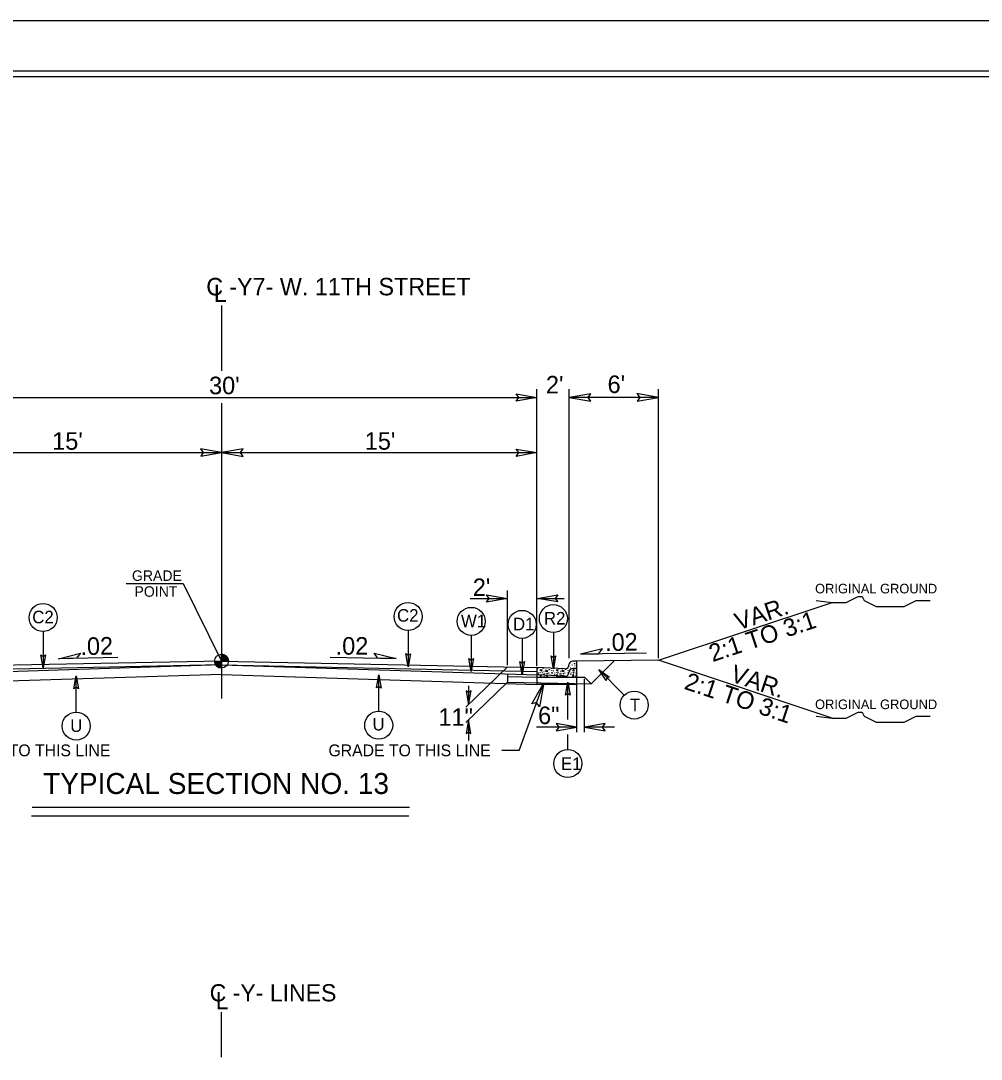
# Model space of a CAD drawing. Extents: x 957297 to 961629, y 830661 to 840840.
# Drawn here: x 959348.5 to 959775.5, y 833917.1 to 834378.9 of the extents above; entities that cross this region are included whole.
import ezdxf

# ---------------------------------------------------------------- set-up
doc = ezdxf.new("R2010")
doc.units = 0
for name, color, linetype in [('Default', 7, 'Continuous'), ('Old_Level_1', 7, 'Continuous'), ('Old_Level_11', 7, 'Continuous'), ('Old_Level_21', 7, 'Continuous'), ('Old_Level_3', 7, 'Continuous'), ('Prop Dimension Text', 7, 'Continuous'), ('Sheet Plot Border Inside CELL', 7, 'Continuous'), ('Sheet Plot Border Outside CELL', 7, 'Continuous'), ('Sheet Typical CELL', 7, 'Continuous'), ('Typical ID Circle CELL', 7, 'Continuous'), ('Typical Terminator CELL', 7, 'Continuous'), ('Typical Text Grade Point CELL', 7, 'Continuous'), ('Typical Text ID Circle CELL', 7, 'Continuous')]:
    doc.layers.add(name, color=color, linetype=linetype)

msp = doc.modelspace()

# ---------------------------------------------------------------- linework, layer by layer
at = {"layer": 'Default'}
for p, q in [((959437.72, 834252.24), (959437.72, 834223.26)), ((959437.72, 834208.87), (959437.72, 834077.5)), ((959437.72, 833918.09), (959437.72, 833938.07))]:
    msp.add_line(p, q, dxfattribs=at)
at = {"layer": 'Old_Level_1'}
for p, q in [((959577.94, 834092.06), (959577.94, 834215.05)), ((959592.24, 834095.46), (959592.24, 834215.05)), ((959632.06, 834095.46), (959632.06, 834215.05)), ((959297.55, 834211.42), (959577.94, 834211.42)), ((959632.06, 834211.42), (959592.24, 834211.42)), ((959297.5, 834186.86), (959437.72, 834186.86)), ((959437.72, 834186.86), (959577.94, 834186.86)), ((959564.8, 834092.3), (959564.8, 834125.5)), ((959548.26, 834122.04), (959564.8, 834122.04)), ((959578, 834122.04), (959590.11, 834122.04)), ((959632.06, 834094.54), (959709.25, 834120.27)), ((959437.72, 834094.16), (959437.72, 834097.22)), ((959626.59, 834097.76), (959597.37, 834097.18)), ((959437.72, 834094.17), (959297.55, 834091.33)), ((959437.72, 834092.44), (959297.55, 834089.61)), ((959437.72, 834092.44), (959297.55, 834088.05)), ((959391.59, 834095.77), (959365.21, 834095.24)), ((959434.66, 834094.16), (959437.72, 834094.16)), ((959437.72, 834094.17), (959577.94, 834091.33)), ((959440.78, 834094.16), (959437.72, 834094.16)), ((959437.72, 834091.11), (959437.72, 834094.16)), ((959437.72, 834094.16), (959437.72, 834091.11)), ((959437.72, 834092.44), (959577.94, 834089.61)), ((959437.72, 834092.44), (959577.94, 834088.05)), ((959486.07, 834095.86), (959515.29, 834095.28)), ((959632.06, 834094.54), (959595.74, 834094.18)), ((959602.01, 834084.02), (959612.34, 834094.35)), ((959709.25, 834068.81), (959632.06, 834094.54)), ((959437.72, 834088.17), (959297.55, 834083.77)), ((959437.72, 834088.17), (959577.88, 834083.77)), ((959564.82, 834091.6), (959546.35, 834073.67)), ((959564.8, 834088.46), (959564.8, 834084.77)), ((959590.33, 834087.43), (959577.94, 834088.05)), ((959577.94, 834088.05), (959577.94, 834083.94)), ((959595.43, 834090.89), (959593.96, 834090.89)), ((959595.74, 834087.33), (959595.74, 834090.59)), ((959564.8, 834084.77), (959546.32, 834066.84)), ((959547.56, 834083.21), (959547.56, 834074.84)), ((959564.8, 834087.32), (959577.94, 834087.06)), ((959564.8, 834084.77), (959602.01, 834084.02)), ((959569.99, 834054.41), (959580.97, 834084.44)), ((959577.94, 834087.06), (959577.94, 834084.51)), ((959577.94, 834083.94), (959595.74, 834083.94)), ((959595.74, 834083.94), (959595.74, 834087.33)), ((959595.74, 834087.06), (959599.04, 834086.99)), ((959595.74, 834062.5), (959595.74, 834086.26)), ((959599.04, 834086.99), (959602.01, 834084.02)), ((959599.04, 834062.5), (959599.04, 834086.26)), ((959547.5, 834068.02), (959547.49, 834058.8)), ((959595.74, 834064.79), (959577.72, 834064.79)), ((959612.38, 834064.79), (959599.04, 834064.79)), ((959569.99, 834054.41), (959562.27, 834054.41)), ((959521.22, 834029.03), (959353.52, 834029.03)), ((959520.94, 834025.23), (959353.24, 834025.23))]:
    msp.add_line(p, q, dxfattribs=at)
for points in [[(959437.76, 834097.22), (959437.76, 834097.22), (959437.76, 834094.16)], [(959437.81, 834097.22), (959437.81, 834094.16)], [(959437.87, 834097.22), (959437.87, 834094.16)], [(959437.94, 834097.21), (959437.94, 834094.16)], [(959438, 834097.21), (959438, 834094.16)], [(959438.06, 834097.21), (959438.06, 834094.16)], [(959438.12, 834097.19), (959438.12, 834094.16)], [(959438.18, 834097.19), (959438.18, 834094.16)], [(959438.23, 834097.17), (959438.23, 834094.16)], [(959438.3, 834097.17), (959438.3, 834094.16)], [(959438.36, 834097.16), (959438.36, 834094.16)], [(959438.42, 834097.14), (959438.42, 834094.16)], [(959438.49, 834097.12), (959438.49, 834094.16)], [(959438.55, 834097.1), (959438.55, 834094.16)], [(959438.61, 834097.09), (959438.61, 834094.16)], [(959438.67, 834097.06), (959438.67, 834094.16)], [(959438.74, 834097.05), (959438.73, 834094.16)], [(959438.79, 834097.03), (959438.79, 834094.16)], [(959438.85, 834097.01), (959438.85, 834094.16)], [(959438.92, 834096.98), (959438.92, 834094.16)], [(959438.98, 834096.96), (959438.98, 834094.16)], [(959439.04, 834096.92), (959439.04, 834094.16)], [(959439.09, 834096.9), (959439.09, 834094.16)], [(959439.15, 834096.87), (959439.15, 834094.16)], [(959439.21, 834096.84), (959439.21, 834094.16)], [(959439.28, 834096.8), (959439.28, 834094.16)], [(959439.34, 834096.76), (959439.34, 834094.16)], [(959439.4, 834096.72), (959439.4, 834094.16)], [(959439.47, 834096.67), (959439.47, 834094.16)], [(959434.68, 834094.16), (959434.68, 834093.84)], [(959434.74, 834094.16), (959434.74, 834093.47)], [(959434.8, 834094.16), (959434.8, 834093.25)], [(959434.86, 834094.16), (959434.86, 834093.07)], [(959434.93, 834094.16), (959434.93, 834092.93)], [(959434.99, 834094.16), (959434.99, 834092.8)], [(959435.05, 834094.16), (959435.05, 834092.68)], [(959435.11, 834094.16), (959435.11, 834092.57)], [(959435.17, 834094.16), (959435.17, 834092.48)], [(959435.23, 834094.16), (959435.23, 834092.39)], [(959435.3, 834094.16), (959435.3, 834092.3)], [(959435.36, 834094.16), (959435.36, 834092.23)], [(959435.42, 834094.16), (959435.42, 834092.17)], [(959435.47, 834094.16), (959435.47, 834092.09)], [(959435.53, 834094.16), (959435.53, 834092.02)], [(959435.6, 834094.16), (959435.6, 834091.97)], [(959435.66, 834094.16), (959435.66, 834091.92)], [(959435.72, 834094.16), (959435.72, 834091.85)], [(959435.78, 834094.16), (959435.78, 834091.81)], [(959435.85, 834094.16), (959435.85, 834091.75)], [(959435.9, 834094.16), (959435.9, 834091.71)], [(959435.96, 834094.16), (959435.96, 834091.66)], [(959436.02, 834094.16), (959436.02, 834091.63)], [(959436.09, 834094.16), (959436.09, 834091.57)], [(959436.15, 834094.16), (959436.15, 834091.54)], [(959436.21, 834094.16), (959436.21, 834091.5)], [(959436.28, 834094.16), (959436.28, 834091.47)], [(959436.33, 834094.16), (959436.33, 834091.45)], [(959436.39, 834094.16), (959436.39, 834091.41)], [(959436.46, 834094.16), (959436.46, 834091.38)], [(959436.52, 834094.16), (959436.52, 834091.36)], [(959436.58, 834094.16), (959436.58, 834091.32)], [(959436.64, 834094.16), (959436.64, 834091.31)], [(959436.7, 834094.16), (959436.7, 834091.28)], [(959436.75, 834094.16), (959436.75, 834091.26)], [(959436.82, 834094.16), (959436.82, 834091.25)], [(959436.88, 834094.16), (959436.88, 834091.22)], [(959436.94, 834094.16), (959436.94, 834091.21)], [(959437, 834094.16), (959437, 834091.2)], [(959437.07, 834094.16), (959437.07, 834091.18)], [(959437.13, 834094.16), (959437.13, 834091.16)], [(959437.19, 834094.16), (959437.19, 834091.16)], [(959437.25, 834094.16), (959437.25, 834091.15)], [(959437.31, 834094.16), (959437.31, 834091.13)], [(959437.38, 834094.16), (959437.38, 834091.13)], [(959437.44, 834094.16), (959437.44, 834091.13)], [(959437.5, 834094.16), (959437.5, 834091.11)], [(959437.56, 834094.16), (959437.56, 834091.11)], [(959437.61, 834094.16), (959437.61, 834091.11)], [(959437.67, 834094.16), (959437.67, 834091.11), (959437.67, 834091.11)], [(959439.52, 834096.64), (959439.52, 834094.16)], [(959439.59, 834096.59), (959439.59, 834094.16)], [(959439.65, 834096.54), (959439.65, 834094.16)], [(959439.71, 834096.49), (959439.71, 834094.16)], [(959439.77, 834096.43), (959439.77, 834094.16)], [(959439.83, 834096.37), (959439.83, 834094.16)], [(959439.9, 834096.31), (959439.9, 834094.16)], [(959439.95, 834096.25), (959439.95, 834094.16)], [(959440.01, 834096.19), (959440.01, 834094.16)], [(959440.07, 834096.12), (959440.07, 834094.16)], [(959440.13, 834096.03), (959440.13, 834094.16)], [(959440.2, 834095.96), (959440.2, 834094.16)], [(959440.26, 834095.87), (959440.26, 834094.16)], [(959440.32, 834095.78), (959440.32, 834094.16)], [(959440.38, 834095.67), (959440.38, 834094.16)], [(959440.44, 834095.57), (959440.44, 834094.16)], [(959440.5, 834095.42), (959440.5, 834094.16)], [(959440.57, 834095.28), (959440.57, 834094.16)], [(959440.63, 834095.12), (959440.63, 834094.16)], [(959440.69, 834094.91), (959440.69, 834094.16)], [(959440.75, 834094.6), (959440.75, 834094.16)]]:
    msp.add_lwpolyline(points, dxfattribs=at)
msp.add_circle((959437.72, 834094.16), 3.06, dxfattribs=at)
for centre, radius, start, end in [((959437.72, 834094.16), 3.06, 359.9905, 89.9905), ((959437.72, 834094.16), 3.06, 179.9905, 269.9905), ((959590.42, 834089.18), 1.76, 267.1376, 358.9266), ((959593.96, 834089.12), 1.78, 90, 178.9266), ((959595.43, 834090.59), 0.309, 0, 90)]:
    msp.add_arc(centre, radius, start, end, dxfattribs=at)
at = {"layer": 'Old_Level_11'}
for p, q in [((959365.21, 834095.24), (959374.96, 834097.67)), ((959374.96, 834097.67), (959373.23, 834095.4)), ((959507.28, 834095.44), (959505.55, 834097.7)), ((959505.55, 834097.7), (959515.29, 834095.28)), ((959607.11, 834099.59), (959597.37, 834097.18)), ((959597.37, 834097.18), (959605.38, 834097.34)), ((959605.38, 834097.34), (959607.11, 834099.59)), ((959373.23, 834095.4), (959365.21, 834095.24)), ((959515.29, 834095.28), (959507.28, 834095.44))]:
    msp.add_line(p, q, dxfattribs=at)
for points in [[(959601.84, 834213.08), (959592.24, 834211.42), (959601.9, 834209.71), (959600.67, 834211.42)], [(959622.45, 834209.77), (959632.06, 834211.42), (959622.4, 834213.13), (959623.62, 834211.42)], [(959447.33, 834188.52), (959437.72, 834186.86), (959447.39, 834185.14), (959446.16, 834186.86)], [(959575.63, 834075.14), (959580.97, 834084.44), (959579.09, 834073.82), (959577.79, 834075.73)]]:
    msp.add_lwpolyline(points, close=True, dxfattribs=at)
at = {"layer": 'Old_Level_21'}
for points in [[(959702.15, 834121.16), (959709.25, 834120.27), (959711.02, 834120.27), (959713.68, 834120.27), (959715.46, 834120.27), (959717.23, 834121.16), (959719.01, 834122.05), (959720.78, 834122.93), (959722.55, 834122.93), (959723.45, 834121.16), (959725.21, 834120.27), (959726.99, 834119.38), (959728.76, 834118.51), (959730.54, 834118.51), (959732.3, 834118.51), (959734.08, 834118.51), (959735.85, 834118.51), (959737.63, 834118.51), (959739.4, 834118.51), (959741.18, 834118.51), (959742.95, 834119.38), (959744.71, 834120.27), (959746.48, 834121.16), (959749.16, 834121.16), (959750.93, 834121.16), (959752.7, 834121.16)], [(959702.15, 834069.69), (959709.25, 834068.81), (959711.02, 834068.81), (959713.68, 834068.81), (959715.46, 834068.81), (959717.23, 834069.69), (959719.01, 834070.59), (959720.78, 834071.47), (959722.55, 834071.47), (959723.45, 834069.69), (959725.21, 834068.81), (959726.99, 834067.92), (959728.76, 834067.04), (959730.54, 834067.04), (959732.3, 834067.04), (959734.08, 834067.04), (959735.85, 834067.04), (959737.63, 834067.04), (959739.4, 834067.04), (959741.18, 834067.04), (959742.95, 834067.92), (959744.71, 834068.81), (959746.48, 834069.69), (959749.16, 834069.69), (959750.93, 834069.69), (959752.7, 834069.69)]]:
    msp.add_lwpolyline(points, dxfattribs=at)
at = {"layer": 'Old_Level_3'}
for p, q in [((959595.43, 834094.18), (959593.96, 834094.18)), ((959595.74, 834090.62), (959595.74, 834093.88)), ((959590.33, 834090.72), (959577.94, 834091.33)), ((959577.94, 834091.33), (959577.94, 834087.06)), ((959579.29, 834090.34), (959579.91, 834090.37)), ((959579.91, 834089.74), (959579.29, 834090.34)), ((959579.52, 834088.16), (959579.32, 834087.5)), ((959579.32, 834087.5), (959580.01, 834087.47)), ((959580.01, 834087.47), (959579.52, 834088.16)), ((959579.91, 834090.37), (959579.91, 834089.74)), ((959581.72, 834089.68), (959582.62, 834089.93)), ((959582.51, 834089.41), (959581.72, 834089.68)), ((959582.45, 834087.83), (959581.85, 834087.41)), ((959582.81, 834087.18), (959582.45, 834087.83)), ((959582.62, 834089.93), (959582.51, 834089.41)), ((959586.51, 834090.34), (959587.14, 834090.37)), ((959587.14, 834089.74), (959586.51, 834090.34)), ((959586.74, 834088.16), (959586.55, 834087.5)), ((959586.55, 834087.5), (959587.23, 834087.47)), ((959587.23, 834087.47), (959586.74, 834088.16)), ((959587.14, 834090.37), (959587.14, 834089.74)), ((959588.95, 834089.68), (959589.84, 834089.93)), ((959589.74, 834089.41), (959588.95, 834089.68)), ((959589.68, 834087.83), (959589.08, 834087.41)), ((959590.04, 834087.18), (959589.68, 834087.83)), ((959589.84, 834089.93), (959589.74, 834089.41)), ((959590.33, 834090.72), (959590.33, 834090.72)), ((959592.16, 834091.83), (959592, 834091.86)), ((959592.03, 834091.99), (959592.16, 834091.83)), ((959593.74, 834090.34), (959594.37, 834090.37)), ((959594.37, 834089.74), (959593.74, 834090.34)), ((959593.96, 834088.16), (959593.78, 834087.5)), ((959593.78, 834087.5), (959594.46, 834087.47)), ((959594.46, 834087.47), (959593.96, 834088.16)), ((959594.37, 834090.37), (959594.37, 834089.74)), ((959595.74, 834087.06), (959595.74, 834090.62)), ((959577.94, 834087.06), (959595.74, 834087.06)), ((959581.85, 834087.41), (959582.81, 834087.18)), ((959589.08, 834087.41), (959590.04, 834087.18))]:
    msp.add_line(p, q, dxfattribs=at)
for centre in [(959592.58, 834093.28), (959593.61, 834092.42), (959593.77, 834093.41), (959594.7, 834093.01), (959594.86, 834092.22), (959595.68, 834092.32), (959578.16, 834089.84), (959578.46, 834091.03), (959578.52, 834088.26), (959578.69, 834088.85), (959579.55, 834089.21), (959579.81, 834088.63), (959580.37, 834089.12), (959580.54, 834090.83), (959580.54, 834087.47), (959581, 834088.4), (959581.13, 834089.54), (959581.32, 834088.59), (959581.42, 834088.03), (959581.89, 834090.17), (959582.45, 834088.59), (959583.14, 834088.88), (959583.44, 834090.34), (959584.17, 834087.93), (959584.59, 834089.91), (959584.63, 834089.05), (959584.73, 834088.76), (959584.89, 834087.77), (959585.39, 834089.84), (959585.75, 834088.26), (959585.92, 834088.85), (959586.78, 834089.21), (959587.04, 834088.63), (959587.6, 834089.12), (959587.77, 834087.47), (959588.23, 834088.4), (959588.35, 834089.54), (959588.55, 834088.59), (959588.65, 834088.03), (959589.11, 834090.17), (959589.67, 834088.59), (959590.37, 834088.88), (959590.67, 834090.34), (959591.39, 834087.93), (959591.72, 834091), (959591.82, 834089.91), (959591.86, 834089.05), (959591.95, 834088.76), (959592.12, 834087.77), (959592.55, 834091.89), (959592.62, 834089.84), (959592.91, 834091.03), (959592.98, 834088.26), (959593.14, 834088.85), (959594, 834089.21), (959594.27, 834088.63), (959594.83, 834089.12), (959594.99, 834090.83), (959594.99, 834087.47), (959595.46, 834088.4), (959595.58, 834089.54), (959581.09, 834087.2), (959588.32, 834087.2), (959595.55, 834087.2)]:
    msp.add_circle(centre, 0.0464, dxfattribs=at)
for centre, radius, start, end in [((959590.42, 834092.47), 1.76, 267.1376, 358.9266), ((959593.96, 834092.4), 1.78, 90, 178.9266), ((959595.43, 834093.88), 0.309, 0, 90), ((959595.55, 834094.1), 0.0464, 169.6531, 280.3469), ((959584.5, 834091), 0.0464, 164.1199, 10.1626), ((959587.77, 834090.83), 0.0464, 162.062, 12.2205), ((959595.78, 834088.59), 0.0464, 150.4173, 209.5827)]:
    msp.add_arc(centre, radius, start, end, dxfattribs=at)
at = {"layer": 'Sheet Plot Border Inside CELL'}
msp.add_lwpolyline([(960390.3, 834356.46), (958723.8, 834356.46), (958723.8, 833301.36), (960390.3, 833301.36)], close=True, dxfattribs=at)
at = {"layer": 'Sheet Plot Border Outside CELL'}
msp.add_lwpolyline([(960394.8, 834378.91), (958710.8, 834378.91), (958710.8, 833278.91), (960394.8, 833278.91)], close=True, dxfattribs=at)
at = {"layer": 'Sheet Typical CELL'}
msp.add_lwpolyline([(960377.8, 834353.91), (958877.8, 834353.91), (958877.8, 833303.91), (960377.8, 833303.91)], close=True, dxfattribs=at)
at = {"layer": 'Typical ID Circle CELL'}
for p, q in [((959358.39, 834107.31), (959358.39, 834091.22)), ((959520.68, 834107.77), (959520.68, 834091.68)), ((959585.26, 834106.84), (959585.26, 834090.75)), ((959548.73, 834105.62), (959548.73, 834089.53)), ((959571.36, 834104.28), (959571.36, 834088.19)), ((959373.11, 834071.5), (959373.11, 834087.58)), ((959507.59, 834071.9), (959507.59, 834087.99)), ((959616.79, 834079.01), (959605.41, 834090.39)), ((959591.67, 834068.15), (959591.67, 834084.85)), ((959591.67, 834054.82), (959591.67, 834061.46))]:
    msp.add_line(p, q, dxfattribs=at)
for centre in [(959358.39, 834113.53), (959520.68, 834113.99), (959548.73, 834111.84), (959571.36, 834110.5), (959585.26, 834113.07), (959621.19, 834074.61), (959373.11, 834065.27), (959507.59, 834065.67), (959591.67, 834048.6)]:
    msp.add_circle(centre, 6.23, dxfattribs=at)
at = {"layer": 'Typical Terminator CELL'}
for points in [[(959568.72, 834213.01), (959577.94, 834211.42), (959568.66, 834209.78), (959569.84, 834211.42)], [(959428.5, 834185.27), (959437.72, 834186.86), (959428.44, 834188.5), (959429.62, 834186.86)], [(959568.72, 834188.45), (959577.94, 834186.86), (959568.66, 834185.22), (959569.84, 834186.86)], [(959555.57, 834123.63), (959564.8, 834122.04), (959555.52, 834120.4), (959556.7, 834122.04)], [(959587.22, 834120.46), (959578, 834122.04), (959587.27, 834123.68), (959586.09, 834122.04)], [(959359.39, 834096.99), (959358.39, 834091.22), (959357.37, 834097.02), (959358.39, 834096.28)], [(959521.67, 834097.44), (959520.68, 834091.68), (959519.66, 834097.48), (959520.68, 834096.74)], [(959549.72, 834095.29), (959548.73, 834089.53), (959547.71, 834095.33), (959548.73, 834094.59)], [(959572.35, 834093.96), (959571.36, 834088.19), (959570.33, 834093.99), (959571.36, 834093.25)], [(959586.26, 834096.52), (959585.26, 834090.75), (959584.24, 834096.55), (959585.26, 834095.81)], [(959372.12, 834081.82), (959373.11, 834087.58), (959374.13, 834081.79), (959373.11, 834082.52)], [(959506.6, 834082.22), (959507.59, 834087.99), (959508.62, 834082.19), (959507.59, 834082.93)], [(959608.79, 834085.61), (959605.41, 834090.39), (959610.24, 834087.02), (959608.99, 834086.81)], [(959590.68, 834079.09), (959591.67, 834084.85), (959592.7, 834079.06), (959591.67, 834079.8)], [(959546.52, 834080.91), (959547.56, 834074.84), (959548.64, 834080.94), (959547.56, 834080.17)], [(959548.54, 834061.95), (959547.5, 834068.02), (959546.42, 834061.92), (959547.49, 834062.7)], [(959586.52, 834063.21), (959595.74, 834064.79), (959586.47, 834066.43), (959587.65, 834064.79)], [(959608.26, 834066.38), (959599.04, 834064.79), (959608.32, 834063.15), (959607.14, 834064.79)]]:
    msp.add_lwpolyline(points, close=True, dxfattribs=at)
at = {"layer": 'Typical Text Grade Point CELL'}
for p, q in [((959395.28, 834128.72), (959420.61, 834128.72)), ((959420.61, 834128.72), (959437.72, 834094.16))]:
    msp.add_line(p, q, dxfattribs=at)

# ---------------------------------------------------------------- texts
at = {"layer": 'Old_Level_1'}
for s, height, p in [("30'", 7.801, (959432.19, 834212.84)), ("15'", 7.801, (959362.45, 834188.15)), ("15'", 7.801, (959501.41, 834188.15)), ('GRADE TO THIS LINE', 5.2473, (959316.2, 834051.85)), ('GRADE TO THIS LINE', 5.2473, (959485.25, 834051.84)), ('TYPICAL SECTION NO. 13', 9.3239, (959358.38, 834035.07))]:
    msp.add_text(s, height=height, dxfattribs=at).set_placement(p)
at = {"layer": 'Old_Level_11'}
for s, height, p in [('GRADE', 4.671, (959397.89, 834129.84)), ('POINT', 4.671, (959399.02, 834122.77)), ('11"', 7.801, (959534.18, 834065.4))]:
    msp.add_text(s, height=height, dxfattribs=at).set_placement(p)
at = {"layer": 'Old_Level_21'}
for p in [(959701.61, 834124.27), (959701.61, 834072.81)]:
    msp.add_text('ORIGINAL GROUND', height=4.2722, dxfattribs=at).set_placement(p)
at = {"layer": 'Old_Level_3'}
for s, height, p in [("2'", 7.801, (959581.95, 834213.19)), ("6'", 7.801, (959609.35, 834213.37)), ('C -Y- LINES', 7.6574, (959432.45, 833942.84)), ('L', 7.66, (959435.09, 833939.39))]:
    msp.add_text(s, height=height, dxfattribs=at).set_placement(p)
for s, rotation, p in [('VAR.', 18.4384, (959667.47, 834107.7)), ('2:1 TO 3:1', 18.4384, (959656.01, 834093.67)), ('VAR.', 341.5616, (959663.44, 834085.33)), ('2:1 TO 3:1', 341.5616, (959642.98, 834081.91))]:
    msp.add_text(s, height=7.801, rotation=rotation, dxfattribs=at).set_placement(p)
at = {"layer": 'Prop Dimension Text'}
for s, height, rotation, p in [('C', 7.77, 0, (959430.92, 834256.79)), ('-Y7- W. 11TH STREET', 7.7675, 0, (959441.13, 834256.81)), ('L', 7.77, 0, (959434.32, 834253.86)), ("2'", 7.801, 0, (959549.43, 834123.1)), ('.02', 7.801, 1.1839, (959608.32, 834098.6)), ('.02', 7.801, 1.1839, (959375.07, 834096.82)), ('.02', 7.801, 360, (959488.47, 834097.03)), ('6"', 7.801, 0, (959578.45, 834066.17))]:
    msp.add_text(s, height=height, rotation=rotation, dxfattribs=at).set_placement(p)
at = {"layer": 'Typical Text ID Circle CELL'}
for s, height, p in [('C2', 5.572, (959353.58, 834110.98)), ('C2', 5.572, (959515.77, 834111.7)), ('R2', 5.572, (959581.07, 834110.44)), ('D1', 5.572, (959567.3, 834107.87)), ('U', 5.57, (959370.46, 834062.65)), ('E1', 5.572, (959588.65, 834045.77))]:
    msp.add_text(s, height=height, dxfattribs=at).set_placement(p)
for s, height, p in [('W1', 5.572, (959544.18, 834109.23)), ('T', 5.57, (959619.28, 834071.86)), ('U', 5.57, (959504.85, 834063.33))]:
    msp.add_text(s, height=height, rotation=360, dxfattribs=at).set_placement(p)

doc.saveas('drawing.dxf')
